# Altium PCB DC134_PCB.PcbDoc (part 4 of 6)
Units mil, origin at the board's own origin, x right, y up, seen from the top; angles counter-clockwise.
Board outline 4000 x 2750 mil, 6 copper layers (L1_Top Layer, L2_GND1, L3_Signal, L4_Plane, L5_GND2, L6_Bottom Layer), stack 60.4 mil thick; 404 components, 244 nets, 1547 pads, 694 vias.
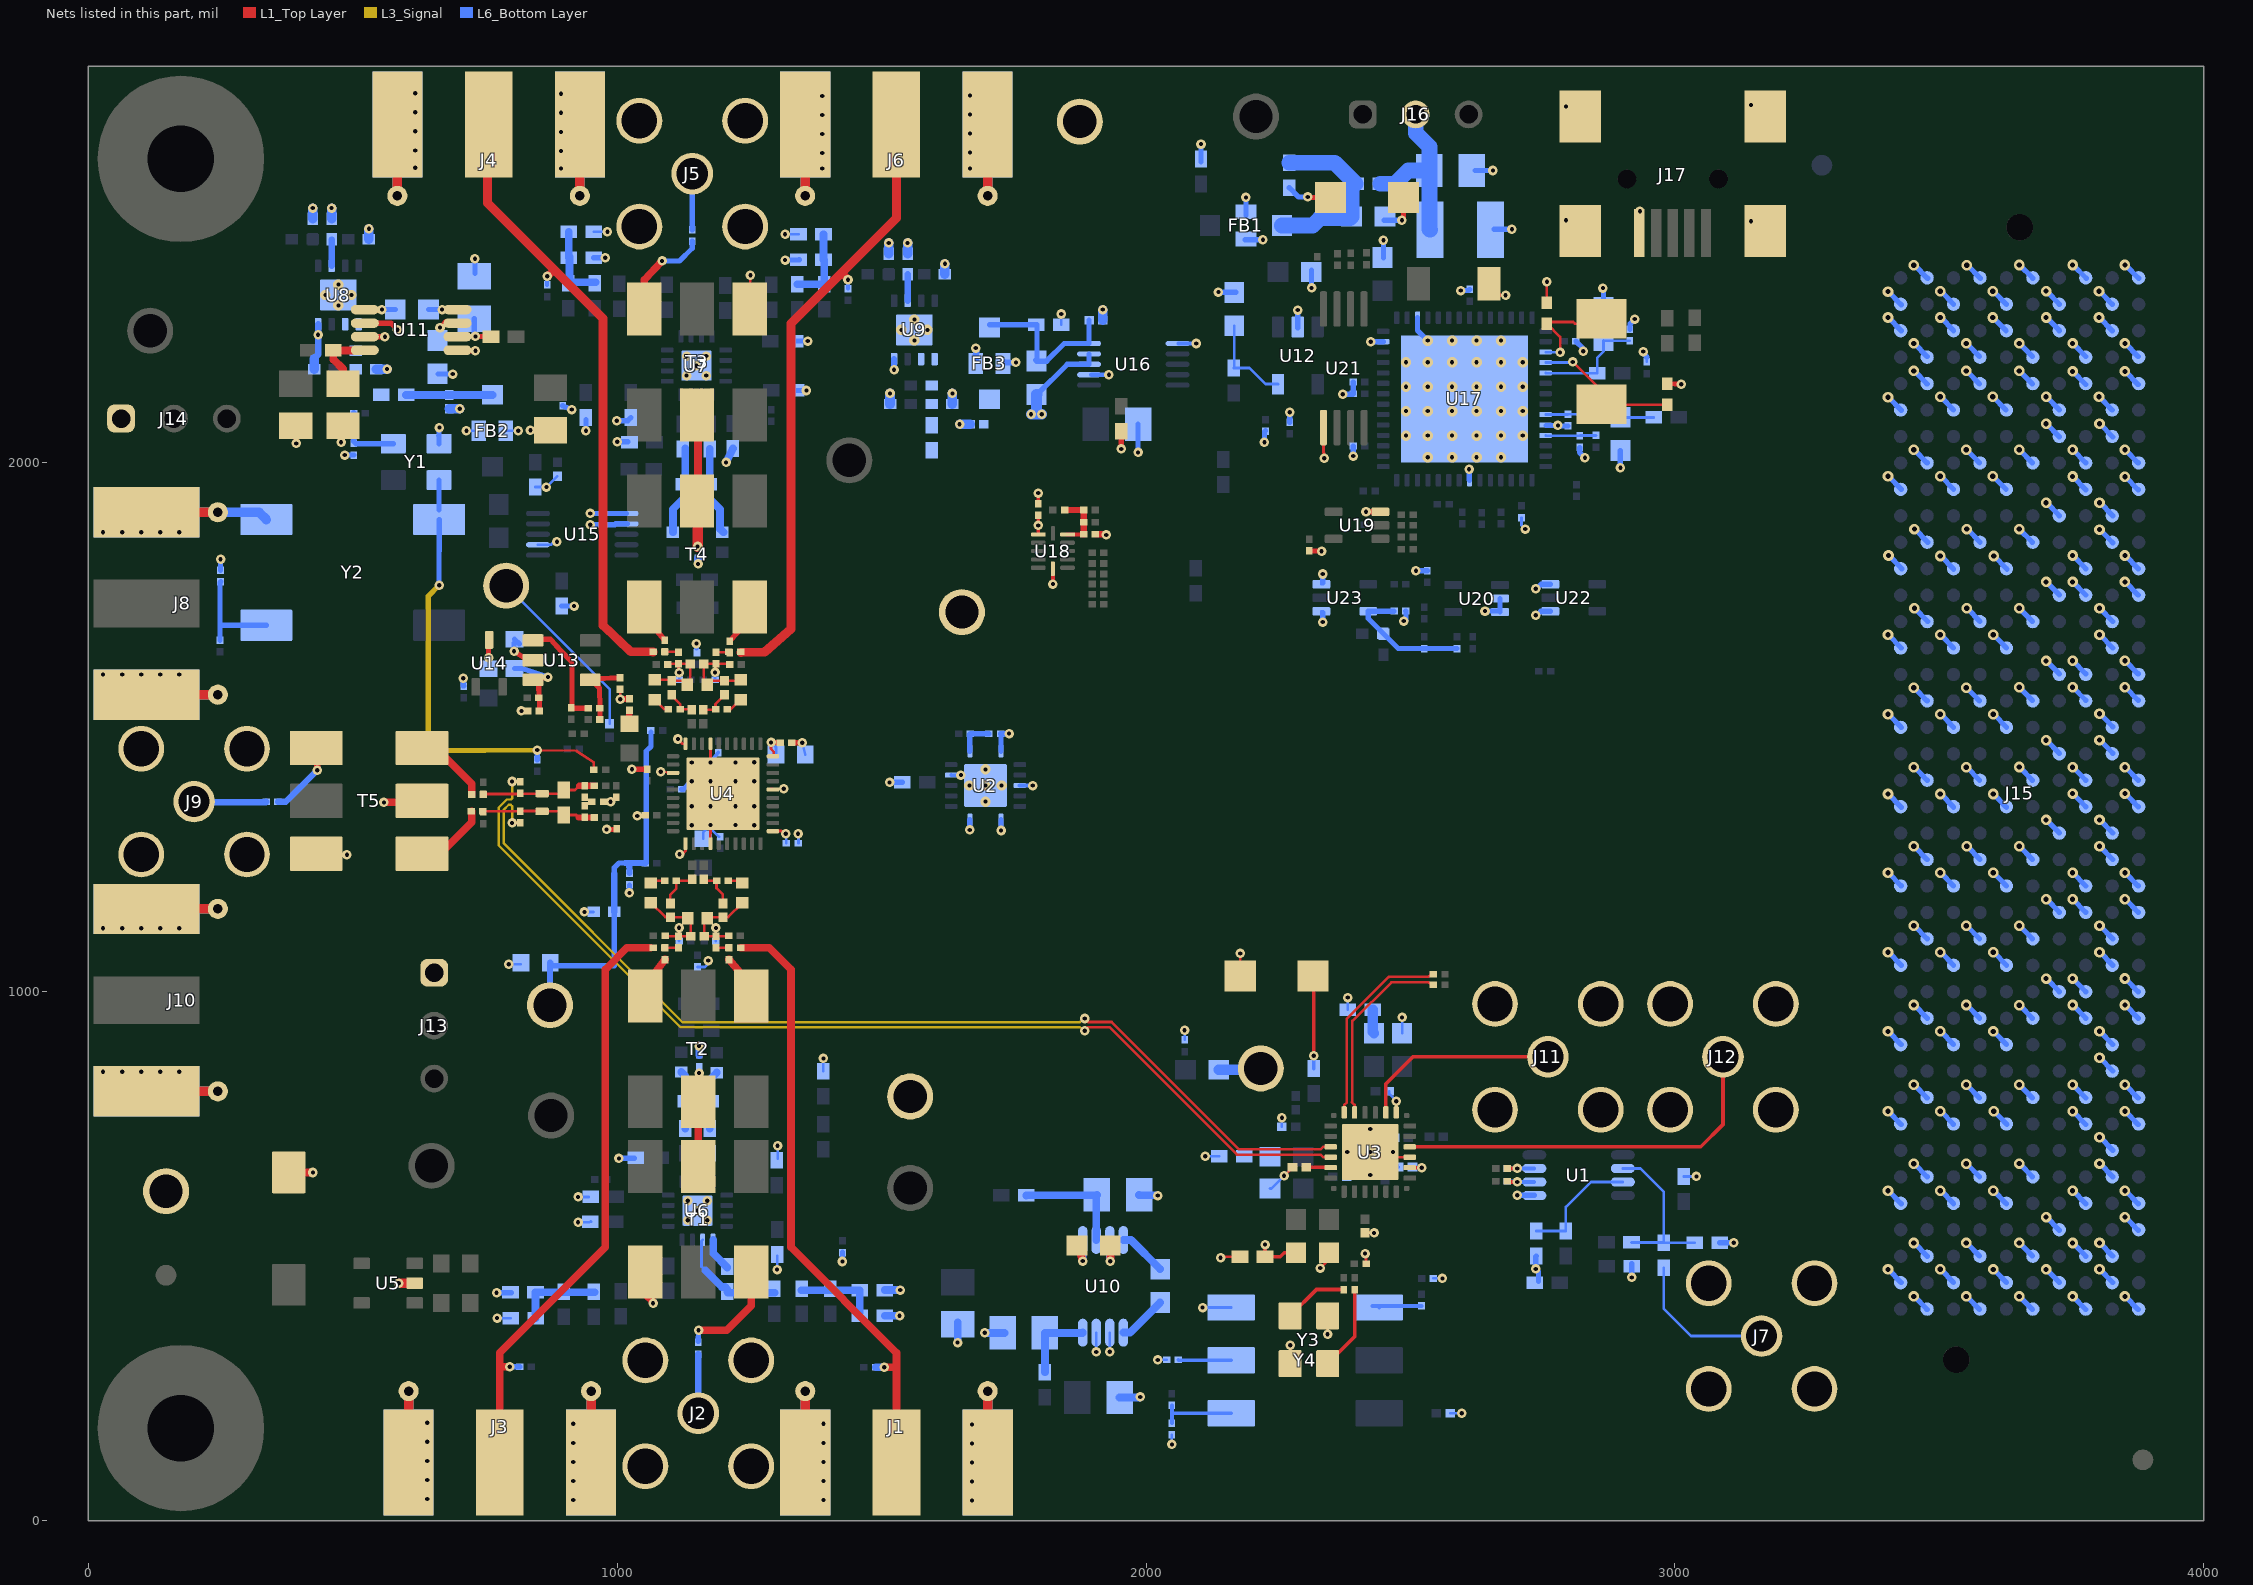
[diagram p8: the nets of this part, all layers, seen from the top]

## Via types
v1: diameter 18, hole 8, L1_Top Layer to L6_Bottom Layer, tented both sides, 448 vias
v2: diameter 20, hole 10, L1_Top Layer to L6_Bottom Layer, tented both sides, 182 vias
v3: diameter 19.68, hole 7.87, L1_Top Layer to L6_Bottom Layer, tented both sides, 42 vias
v4: diameter 19.68, hole 7.87, L1_Top Layer to L6_Bottom Layer, 20 vias
v5: diameter 18, hole 8, L1_Top Layer to L6_Bottom Layer, 2 vias

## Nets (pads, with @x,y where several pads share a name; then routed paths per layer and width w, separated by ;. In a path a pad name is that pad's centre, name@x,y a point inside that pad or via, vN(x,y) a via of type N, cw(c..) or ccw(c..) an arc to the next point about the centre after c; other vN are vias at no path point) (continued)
GND: C5.1 C7.1 C13.1 C15.1 C18.1 C19.1 C20.1 C22.1 C24.1 C27.2 C28.2 C29.2 C30.2 C31.2 C32.2 C33.2 C34.2 C35.2 C36.2 C37.2 C38.2 C39.2 C40.2 C41.2 C42.2 C43.2 C45.2 C46.2 C47.2 C48.2 C49.1 C50.1 C53.2 C54.1 C55.1 C58.2 C59.2 C60.2 C61.2 C62.2 C63.2 C64.2 C65.2 C66.2 C67.2 C68.2 C69.2 C70.2 C71.1 C72.1 C73.1 C74.2 C75.2 C76.2 C77.1 C78.2 C79.2 C80.2 C83.2 C84.2 C85.2 C86.1 C87.2 C88.2 C89.2 C90.2 C91.2 C92.2 C93.2 C94.2 C95.2 C96.2 C97.2 C99.2 C100.2 C101.2 C102.2 C103.2 C104.2 C105.1 C106.1 C107.1 C108.2 C109.1 C110.1 C111.2 C112.1 C113.2 C114.1 C115.2 C116.2 C117.2 C118.2 C119.2 C120.1 C121.2 C122.2 C123.2 C124.2 C125.1 C126.1 D1.1 D2.1 FB1.2 FB2.2 FB3.2 J1.2 J1.3 J1.4 J1.5 J2.2 J2.3 J2.4 J2.5 J3.2 J3.3 J3.4 J3.5 J4.2 J4.3 J4.4 J4.5 J5.2 J5.3 J5.4 J5.5 J6.2 J6.3 J6.4 J6.5 J7.2 J7.3 J7.4 J7.5 J8.2 J8.3 J8.4 J8.5 J9.2 J9.3 J9.4 J9.5 J10.2 J10.3 J10.4 J10.5 J11.2 J11.3 J11.4 J11.5 J12.2 J12.3 J12.4 J12.5 J13.1 J14.1 J15.A1 J15.A4 J15.A5 J15.A8 J15.A9 J15.A12 J15.A13 J15.A16 J15.A17 J15.A20 J15.A21 J15.A24 J15.A25 J15.A28 J15.A29 J15.A32 J15.A33 J15.A36 J15.A37 J15.A40 J15.B2 J15.B3 J15.B6 J15.B7 J15.B10 J15.B11 J15.B14 J15.B15 J15.B18 J15.B19 J15.B22 J15.B23 J15.B26 J15.B27 J15.B30 J15.B31 J15.B34 J15.B35 J15.B38 J15.B39 J15.C1 J15.C4 J15.C5 J15.C8 J15.C9 J15.C12 J15.C13 J15.C16 J15.C17 J15.C20 J15.C21 J15.C24 J15.C25 J15.C28 J15.C29 J15.C32 J15.C33 J15.C36 J15.C38 J15.C40 J15.D2 J15.D3 J15.D6 J15.D7 J15.D10 J15.D13 J15.D16 J15.D19 J15.D22 J15.D25 J15.D28 J15.D37 J15.D39 J15.E1 J15.E4 J15.E5 J15.E8 J15.E11 J15.E14 J15.E17 J15.E20 J15.E23 J15.E26 J15.E29 J15.E32 J15.E35 J15.E38 J15.E40 J15.F2 J15.F3 J15.F6 J15.F9 J15.F12 J15.F15 J15.F18 J15.F21 J15.F24 J15.F27 J15.F30 J15.F33 J15.F36 J15.F39 J15.G1 J15.G4 J15.G5 J15.G8 J15.G11 J15.G14 J15.G17 J15.G20 J15.G23 J15.G26 J15.G29 J15.G32 J15.G35 J15.G38 J15.G40 J15.H2 J15.H3 J15.H6 J15.H9 J15.H12 J15.H15 J15.H18 J15.H21 J15.H24 J15.H27 J15.H30 J15.H33 J15.H36 J15.H39 J15.J1 J15.J4 J15.J5 J15.J8 J15.J11 J15.J14 J15.J17 J15.J20 J15.J23 J15.J26 J15.J29 J15.J32 J15.J35 J15.J38 J15.J40 J15.K2 J15.K3 J15.K6 J15.K9 J15.K12 J15.K15 J15.K18 J15.K21 J15.K24 J15.K27 J15.K30 J15.K33 J15.K36 J15.K39 J17.5 J17.6 J17.7 J17.8 J17.9 R33.1 R37.1 R39.1 R44.1 R46.1 R54.1 R55.1 R58.1 R62.1 R67.1 R68.2 R69.1 R70.2 R71.1 R73.1 R74.1 R78.1 R81.2 R89.1 R94.2 R95.1 R98.2 R106.1 R111.2 R112.1 R121.1 R122.1 R127.1 R132.1 R154.1 R175.1 R176.1 S1.1 T1.1 T3.1 T5.3 T5.5 TP3.1 TP4.1 TP5.1 U1.5 U2.1 U2.5 U2.8 U2.11 U2.14 U2.15 U3.9 U3.13 U3.25 U4.3 U4.11 U4.14 U4.26 U4.37 U4.40 U4.41 U5.2 U6.17@1151.92,586.12 U7.17@1149.84,2184 U8.4 U8.9 U9.4 U9.9 U10.2 U10.3 U10.5 U11.2 U11.3 U11.5 U12.2 U13.2 U14.3 U15.1 U15.2 U15.7 U16.1 U16.7 U17.10 U17.21 U17.41 U17.45 U17.57 U18.6 U19.3 U20.2 U20.3 U21.5 U22.1 U22.3 U23.1 U23.3 Y1.2 Y2.2 Y3.2 Y3.4 Y4.3 | length 11308.1
  L1_Top Layer w5: T5.3@424,1259 v1(489,1259) ; R127.1@1005.4,1572 1006,1571.4 v1(1006,1553) ; v1(1082.5,1416) U4.3@1103.84,1414.07 ; U4.3@1103.54,1414.37 U4.3@1103.84,1414.07 ; U4.3@1103.91,1414 U4.3@1103.84,1414.07 ; U4.3@1105.63,1413.91 U4.3@1103.84,1414.07 ; v1(1115,1478) 1123.97,1469.03 U4.40@1129.25,1469.03 ; v1(1118.08,1260) 1123.13,1260 1129.25,1266.12 U4.11@1129.25,1280.06 ; U4.41@1160.66,1414 U4.41@1200.12,1374.54 U4.41@1208.45,1382.87 ; U4.14@1175.98,1278.17 1176,1280.06 U4.41@1176.37,1315.49 ; U4.41@1176.38,1434.06 U4.37@1176.38,1469.49 ; T3.1@1251,2291 1252,2292 v1(1252,2355) ; U4.26@1292.22,1384 1290.64,1382.42 1294.59,1382.67 v1(1315,1384) ; U4.26@1294.36,1383 U4.26@1294.49,1382.87 ; v1(2141,497) 2143,499 C27.2@2177.88,499 ; D1.1@2178.1,1030 v1(2178.1,1072.48) ; v1(2261,651.99) R73.1@2277.01,668 ; Y3.2@2272.57,296.72 v1(2272.57,331.57) ; v1(2329.57,477.57) 2346.26,494.26 C28.2@2346.26,506.5 ; U21.5@2335.61,2066.8 2335.61,2019.41 2337,2018.03 v1(2337,2009) ; v1(2343.43,352.43) Y3.4@2343.43,387.28 ; v1(2414.16,505) 2416.02,501.98 R70.2@2416.02,486 ; C29.2@2414.16,544.01 v1(2431.2,544.01) ; v3(2424,697) 2433.84,687.16 U3.9@2498.8,687.16 ; U3.13@2473.21,771.8 v1(2473.21,793.21) ; C104.2@2648.93,2339 2670.93,2317 ; C104.2@2665.93,2316 v1@2675,2316 ; C118.2@2758,2302.69 v1(2758,2342.5) ; J17.5@2933.01,2416.64 J17.5@2934,2417.63
  L1_Top Layer w7: C116.2@1796.24,1924.02 v1(1796.24,1943) ; v1(1824,1771) U18.6@1824,1799.83
  L1_Top Layer w10: v1(393,2037) C95.2@393,2075 ; v1(478,2039) C96.2@478,2077 ; U11.3@522.9,2238.7 v1(560.9,2238.7) ; U11.2@522.9,2264.29 572.21,2264.29 v1(584.5,2252) ; U11.5@694,2212 v1(732,2212) ; v1(756.78,1632) 756.78,1664.07 U14.3@758,1665.29 ; v1(805,1644) 828.52,1629 U13.2@850.71,1629 ; v1(819,1531) R132.1@830.98,1531 ; v1(836,2062) C90.2@874,2062 ; v1(980,1307) R54.1@999.87,1307 ; v1(1028,1421) C45.2@1057,1421.02 ; C37.2@1332.02,1471 v1(1350,1471) ; v1(1953,2026.5) C103.2@1953,2059.88 ; C121.2@2308.59,1833.98 2310.59,1833.98 v1(2332,1833) ; U21.5@2335.61,2066.8 U21.5@2337,2065.41 ; v1(2416,1907.59) U19.3@2443.29,1907.59 U19.3@2445.29,1907.59 ; v1(2484,2459) 2486.9,2461.9 D2.1@2486.9,2502 ; J17.5@2934,2417.63 v1(2934,2476) ; C119.2@2982,2150.5 2986.03,2150.3 v1(3012,2149)
  L1_Top Layer w12: v1(1006,1553) R78.1@1023.34,1553.85 ; C115.2@1906.02,1865 v1@1924,1865
  L1_Top Layer w15: S1.1@379,658.3 v1(424.7,658.3) ; v1(559,1358) T5.5@620,1359 ; T1.1@1053.37,470 1053.37,428.63 v1@1069,413 ; C91.2@1870.89,520.89 v1(1880.39,490.89)
  L1_Top Layer w18: v1(587.2,449) U5.2@617.2,449
  L6_Bottom Layer w5: J4.4@574,2704.62 577.38,2708 J4.4@603,2708 ; Y1.2@660.31,2051.31 Y1.2@661,2052 ; v1(714.89,2060.89) FB2.2@738.41,2060.89 ; v5(773,383) R94.2@798.88,383 ; FB2.2@789.59,2060.89 v1(813,2060.89) ; v1(795,1052) C47.2@817.13,1052 ; C75.2@845,1954.38 v1(866.38,1954.38) C76.2@887,1975.01 ; U15.7@850.34,1845.39 875,1845.39 880.68,1851.08 v1(886,1851.08) ; v1(926,564.01) C65.2@947.31,564.01 ; v1(926,612) C66.2@946.08,612 ; v1(938,1151) C46.2@955.31,1151 ; C65.2@949.76,566 C65.2@950.45,565.31 ; R98.2@955.62,2437 v1(981.5,2437) ; C5.1@1152,1046.98 1166,1046.98 1172.44,1053.42 v1(1172.44,1059) ; C43.2@1163,1289.56 1163,1301.99 v4(1176.5,1315.49) ; v4@1179.73,1306.29 C41.2@1193,1293.02 ; v1(1302.45,474.76) C59.2@1302.45,500.38 ; C60.2@1303.45,684.58 v1(1303.45,709) ; v1(1317.5,2432.5) R111.2@1342.88,2432.5 ; C38.2@1343,1281 v1@1343,1298.02 ; v1(1350,1471) C39.2@1355.43,1448.56 ; R89.1@1390,849.58 v1(1390,874) ; C79.2@1839.62,2261 v1(1839.62,2281.62) ; v1(1905.98,319.02) U10.3@1905.98,355.4 ; v1(1931.57,319.45) U10.2@1931.57,355.4 ; v1@1988,233 v1(1989,234) ; v1(2022,304) R68.2@2038.98,304 ; v1(2049,144) R69.1@2049,161.98 ; C100.2@2073,909.02 v1(2073,927.15) ; v1(2107,403) Y4.3@2161.04,403 ; v1(2112,689) C31.2@2138.38,689 ; C32.2@2234.45,628 2237.01,628 v1(2261,651.99) ; R58.1@2257.01,745 v1(2257.01,762.01) ; C86.1@2272,2077.11 C86.1@2272.09,2077.02 ; U23.1@2331.71,1719.43 U23.1@2334,1717.14 ; U23.3@2331.71,1770.61 U23.3@2334.02,1772.93 ; C33.2@2379.49,650.15 2420.45,650.15 v3(2424,653.69) ; C34.2@2381.38,966 v1(2381.38,989) ; C107.1@2390.98,2130 C107.1@2391.98,2131 ; v1@2412.07,504.07 v1@2413,505 ; C36.2@2459.99,811.75 2459.99,806.43 v1(2473.21,793.21) ; R74.1@2470.01,724 2470.01,699.7 v3(2467.31,697) 2452,681.69 R62.1@2452,670.99 2475.49,670.99 R71.1@2478.01,668.47 ; C35.2@2484.32,921.5 v1(2484.32,951.52) ; R67.1@2543.52,458 v1(2560.5,458) ; C30.2@2574.99,203 v1(2597,203) ; U20.3@2667.45,1719.98 U20.3@2669.4,1718.03 ; C106.1@2710,1896.57 2710,1882 v1(2717,1875) ; v1(2737,1712) v1@2738,1711 ; v1(2737,1762) v1@2738.41,1762 ; U17.10@2755.56,2071.79 U17.10@2756.35,2071 ; v1(2779,2071) v1@2780.02,2069.98 ; v1(2827,2211) v1@2827,2216.02 ; v1(2864,2330.61) v1@2865,2329.61 ; v1@2940.17,2206.83 v1(2940.17,2210.62) ; R154.1@2947,2191.02 2947,2200 ; v1(3040.77,650.77) C22.1@3017,650.77 3040.77,651 v1@3041,651
  L6_Bottom Layer w7: v4@1176.38,1434.06 1190.79,1452.14 1191,1452.4 C42.2@1191,1451.98 ; U2.5@1631.51,1409.88 U2.5@1631.51,1409.73 v1(1650,1409.73)
  L6_Bottom Layer w8: U2.11@1761.44,1390.04 1761.48,1390 v1(1786,1390) ; U16.7@1896.62,2166.81 v1(1930,2166.81) ; U16.1@2061.62,2225.87 v1(2095,2225.87)
  L6_Bottom Layer w10: R39.1@250,1797.02 v1(250,1818) ; v1(485,2015) R33.1@502,2014.98 ; C92.2@661.69,2168 v1(689,2168) ; Y1.2@663.31,2036.45 v1@663.31,2066.31 ; v1(709,1593) 709,1578.81 C97.2@709.78,1578.02 ; C89.2@731,2358.69 v1(731,2386) ; v1(772,431) C53.2@800.38,431 ; v1(805,1644) C101.2@805,1659.04 ; C101.2@806,1666.56 C101.2@815,1657.56 ; C102.2@895,1729.38 v1(918.62,1729.38) ; R112.1@897,2107.98 v1(914,2101) ; v1(941,2060.89) C61.2@941,2081.64 ; v1@949,1883 v1(949.08,1883) 993.45,1883 ; v1(949.08,1904.45) U15.1@1017.66,1904.45 ; C54.1@955.62,2388 v1(977.38,2388) ; U15.2@995.45,1883.24 997.21,1885 U15.2@1019.66,1885 ; v1(999.38,2080) 1020.13,2080 C62.2@1026.09,2085.96 ; v1(1000.28,2040) R106.1@1020.66,2040 ; v1(1003.45,685) C50.1@1032.83,685 ; v1(1023.33,1187) C48.2@1023.33,1201.87 ; C40.2@1122.02,1383 1125.32,1383 v4@1140.94,1398.62 ; v1@1150,1650.02 v1(1150,1658.55) ; v1(1317.5,2383.5) C58.2@1344.38,2384.38 ; C63.2@1336.62,2230.5 v1(1360.5,2230.5) ; C64.2@1338.62,2137 v1(1358,2137) ; v1(1426,490) R95.1@1426,508.1 ; v1(1515,1396) C18.1@1539.38,1396 ; v1(1666.94,1306) U2.1@1666.94,1325.08 ; v1(1726,1305) U2.14@1726,1325.08 ; U2.8@1726,1455 1726,1487.21 R55.1@1725.02,1488.19 v1(1741.19,1488.19) ; v1(1985,2020) C85.2@1985,2073 ; C70.2@2104,2569.62 C70.2@2104,2574.62 v1(2104,2603) ; v1(2137,2323) C84.2@2170.38,2323 ; FB1.2@2187.62,2422 v1(2221,2422) ; FB1.2@2189,2468.62 FB1.2@2189,2474.59 v1(2189,2502) ; v1(2224,2039) 2224,2058.89 C123.2@2226,2060.89 ; C86.1@2272,2077.11 v1(2272,2096) ; U12.2@2287,2255.62 v1(2287,2289) ; v1(2313,2331) C83.2@2313,2364.38 ; v1(2334,1699) U23.1@2334,1717.14 ; U23.3@2334,1772.95 v1(2334,1790) ; v1(2372,2130) C107.1@2390.98,2130 ; v1(2391.98,2013.05) C110.1@2391.98,2032 ; C107.1@2391.98,2131 C120.1@2391.98,2153.12 ; v1(2425,2229.27) U17.41@2448.47,2229.27 ; C108.2@2449.02,2387.62 v1(2449.02,2421) ; C69.2@2450.62,2459 v1(2484,2459) ; v1@2484.85,1701 v1(2487.17,1701) ; C124.2@2491.02,1720 2491.68,1719.29 v1@2491.68,1702 ; v1(2510.39,1796.02) C122.2@2532,1796.02 ; U17.45@2513.43,2274.54 2513.44,2250.65 v3(2532.75,2231.33) ; v1(2595,2326) 2609.98,2326 C105.1@2612,2328.02 ; v1(2611,1988) 2611,1968.32 U17.21@2611.86,1967.46 ; C68.2@2622.62,2553 v1(2656,2553) ; v1(2641,1720) U20.3@2667.43,1720 ; C67.2@2658.62,2441.91 v1(2692,2441.91) ; U20.3@2669.4,1718.03 U20.2@2669.4,1743.62 ; v1(2702,615.15) 2733.95,615.15 U1.5@2734.34,614.76 ; R44.1@2738,500.38 2737,499.38 v1(2737,476) 2742.38,470.62 C19.1@2742.38,452 ; v1@2738,1711 2746.41,1719.41 U22.1@2764.71,1719.41 ; v1@2738.41,1762 2747,1770.59 U22.3@2764.71,1770.59 ; U17.10@2756.35,2071 v1(2779,2071) ; v1@2780.02,2069.98 C112.1@2798,2069.98 ; C109.1@2813.02,2230 v1@2827,2216.02 ; C117.2@2820,2029.35 2820,2020 v1(2830,2010) ; C113.2@2865,2294.5 v1@2865,2329.61 ; v1(2897,1991) C111.2@2897,2023.5 ; C114.1@2915,2253.02 2915,2263 v1(2924,2272) ; v1(2918.62,460) C20.1@2918.62,481 C20.1@2918.62,486.38 ; v1@2940.17,2206.83 2947,2200 ; R37.1@3085,525.62 v1(3111.38,525.62) ; v2@3404,475 3427.59,450.57 J15.K39@3428,450.15 ; v2@3404,624 3427.09,600.09 J15.K36@3428,599.15 ; v2@3404,774 3427.09,750.09 J15.K33@3428,749.15 ; v2@3404,925 3427.59,900.57 J15.K30@3428,900.15 ; v2@3404,1075 3427.59,1050.57 J15.K27@3428,1050.15 ; v2@3404,1225.17 3427.67,1200.65 J15.K24@3428,1200.31 ; v2@3404,1374 3427.09,1350.09 J15.K21@3428,1349.15 ; v2@3404,1524.8 3427.49,1500.47 J15.K18@3428,1499.95 ; v2@3404,1675 3427.59,1650.57 J15.K15@3428,1650.15 ; v2@3404,1975 3427.59,1950.57 J15.K9@3428,1950.15 ; v2@3404,2124.34 3427.26,2100.25 J15.K6@3428,2099.49 ; v2@3404,2275 3427.59,2250.57 J15.K3@3428,2250.15 ; v2@3404,2324 3427.09,2300.09 J15.K2@3428,2299.15 ; v2@3405,1825 3428.11,1801.07 J15.K12@3429,1800.15 ; v2@3453,424 3476.57,399.59 J15.J40@3477,399.15 ; v2@3453,525 J15.J38@3477,500.15 ; v2@3453,675 J15.J35@3477,650.15 ; v2@3453,824 3476.57,799.59 J15.J32@3477,799.15 ; v2@3453,975.06 J15.J29@3477,950.21 ; v2@3453,1125 J15.J26@3477,1100.15 ; v2@3453,1274.98 J15.J23@3477,1250.13 ; v2@3453,1424.76 J15.J20@3477,1400 J15.J20@3477,1399.9 ; v2@3453,1575 J15.J17@3477,1550.15 ; v2@3453,2025 J15.J8@3477,2000.15 ; v2@3453,2174 3476.57,2149.59 J15.J5@3477,2149.15 ; v2@3453,2226 J15.J4@3477,2201.15 ; v2@3453,2374 J15.J1@3478,2349 ; v2@3454,1725 3477.59,1700.57 J15.J14@3478,1700.15 ; v2@3454,1875 3477.59,1850.57 J15.J11@3478,1850.15 ; v2@3503,475.15 J15.H39@3527,450.3 ; v2@3503,624 3526.57,599.59 J15.H36@3527,599.15 ; v2@3503,774 3526.57,749.59 J15.H33@3527,749.15 ; v2@3503,925.15 J15.H30@3527,900.3 ; v2@3503,1075 J15.H27@3527,1050.15 ; v2@3503,1225.17 J15.H24@3527,1200.31 ; v2@3503,1374 3526.57,1349.59 J15.H21@3527,1349.15 ; v2@3503,1525 J15.H18@3527,1500.15 ; v2@3503,1675 J15.H15@3527,1650.15 ; v2@3503,1824 3526.57,1799.59 J15.H12@3527,1799.15 ; v2@3503,1975 J15.H9@3527,1950.15 ; v2@3503,2125 J15.H6@3527,2100.15 ; v2@3503,2275 J15.H3@3527,2250.15 ; v2@3503,2324.85 J15.H2@3527,2300 ; v2@3552,424 J15.G40@3576,399.15 ; v2@3552,525.15 J15.G38@3576,500.3 ; v2@3552,675 J15.G35@3576,650.15 ; v2@3552,824 J15.G32@3576,799.15 ; v2@3552,975 J15.G29@3576,950.15 ; v2@3552,1125 J15.G26@3576,1100.15 ; v2@3552,1424.78 J15.G20@3576,1399.92 ; v2@3552,1575 J15.G17@3576,1550.15 ; v2@3552,2025 J15.G8@3576,2000.15 ; v2@3552,2174 J15.G5@3576,2149.15 ; v2@3552,2226 J15.G4@3576,2201.15 ; v2@3553,1274.98 J15.G23@3577,1250.13 ; v2@3553,1725 J15.G14@3577,1700.15 ; v2@3553,1875 J15.G11@3577,1850.15 ; v2@3553,2374 J15.G1@3578,2349 ; v2@3602,1975 J15.F9@3626,1950.15 ; v2@3602,2125 J15.F6@3626,2100.15 ; v2@3602,2275 J15.F3@3626,2250.15 ; v2@3602,2324.85 J15.F2@3627,2299.85 ; v2@3603,475 J15.F39@3627,450.15 ; v2@3603,624 3626.57,599.59 J15.F36@3627,599.15 ; v2@3603,925 J15.F30@3627,900.15 ; v2@3603,1075 J15.F27@3627,1050.15 ; v2@3603,1225 J15.F24@3627,1200.15 ; v2@3603,1374 3626.57,1349.59 J15.F21@3627,1349.15 ; v2@3603,1525 J15.F18@3627,1500.15 ; v2@3603,1675 J15.F15@3627,1650.15 ; v2@3604,774 3627.09,750.09 J15.F33@3628,749.15 ; v2@3604,1824 3627.09,1800.09 J15.F12@3628,1799.15 ; v2(3651,1875) J15.E11@3676,1850 ; v2@3652,424 J15.E40@3676,399.15 ; v2@3652,525.15 J15.E38@3676,500.3 ; v2@3652,675.15 J15.E35@3676,650.3 ; v2@3652,824 J15.E32@3676,799.15 ; v2@3652,974.8 J15.E29@3676,949.95 ; v2@3652,1125 J15.E26@3676,1100.15 ; v2@3652,1275.18 J15.E23@3676,1250.33 ; v2@3652,1425 J15.E20@3676,1400.15 ; v2@3652,1575.67 J15.E17@3676,1550.82 ; v2@3652,1725 J15.E14@3676,1700.15 ; v2@3652,2025 J15.E8@3676,2000.15 ; v2@3652,2174 J15.E5@3676,2149.15 ; v2@3652,2226 J15.E4@3676,2201.15 ; v2@3652,2374.22 J15.E1@3677,2349.22 ; v2@3703,475 J15.D39@3727,450.15 ; v2@3703,574 3726.57,549.59 J15.D37@3727,549.15 ; v2@3703,1025 J15.D28@3727,1000.15 ; v2@3703,1175.17 J15.D25@3727,1150.31 ; v2@3703,1325 J15.D22@3727,1300.15 ; v2@3703,1475.61 J15.D19@3727,1450.75 ; v2@3703,1625.67 J15.D16@3727,1600.82 ; v2@3703,1775 J15.D13@3727,1750.15 ; v2@3703,1925 J15.D10@3727,1900.15 ; v2@3703,2074.26 3726.7,2049.71 J15.D7@3727,2049.4 ; v2@3703,2125 J15.D6@3727,2100.15 ; v2@3703,2275 J15.D3@3727,2250.15 ; v2@3703,2325 J15.D2@3727,2300 ; v2@3753,424 3776.57,399.59 J15.C40@3777,399.15 ; v2@3753,525 J15.C38@3777,500.15 ; v2@3753,624 3776.57,599.59 J15.C36@3777,599.15 ; v2@3753,774 3776.57,749.59 J15.C33@3777,749.15 ; v2@3753,824 3776.57,799.59 J15.C32@3777,799.15 ; v2@3753,975 J15.C29@3777,950.15 ; v2@3753,1025 J15.C28@3777,1000.15 ; v2@3753,1175 J15.C25@3777,1150.15 ; v2@3753,1225 J15.C24@3777,1200.15 ; v2@3753,1374.76 J15.C21@3777,1350 J15.C21@3777,1349.9 ; v2@3753,1424.76 J15.C20@3777,1400 J15.C20@3777,1399.9 ; v2@3753,1576 J15.C17@3777,1551.15 ; v2@3753,1626 J15.C16@3777,1601.15 ; v2@3753,1775 J15.C13@3777,1750.15 ; v2@3753,1825 J15.C12@3777,1800.15 ; v2@3753,1974.42 3776.78,1949.79 J15.C9@3777,1949.57 ; v2@3753,2025 J15.C8@3777,2000.15 ; v2@3753,2173 3776.07,2149.11 J15.C5@3777,2148.15 ; v2@3753,2226 J15.C4@3777,2201.15 ; v2@3753,2374.22 J15.C1@3778,2349.22 ; v2@3803,2125 J15.B6@3827,2100.15 ; v2@3803,2275 J15.B3@3827,2250.15 ; v2@3803,2324.85 J15.B2@3827,2300 ; v2@3804,475.15 3827.67,450.64 J15.B39@3828,450.3 ; v2@3804,525.15 3827.67,500.64 J15.B38@3828,500.3 ; v2@3804,675.15 3827.67,650.64 J15.B35@3828,650.3 ; v2@3804,725.15 3827.67,700.64 J15.B34@3828,700.3 ; v2@3804,875.15 3827.67,850.64 J15.B31@3828,850.3 ; v2@3804,925.15 3827.67,900.64 J15.B30@3828,900.3 ; v2@3804,1075 3827.59,1050.57 J15.B27@3828,1050.15 ; v2@3804,1125 3827.59,1100.57 J15.B26@3828,1100.15 ; v2@3804,1275 3827.59,1250.57 J15.B23@3828,1250.15 ; v2@3804,1325 3827.59,1300.57 J15.B22@3828,1300.15 ; v2@3804,1476 J15.B19@3828,1451.15 ; v2@3804,1526 J15.B18@3828,1501.15 ; v2@3804,1675 3827.59,1650.57 J15.B15@3828,1650.15 ; v2@3804,1725 3827.59,1700.57 J15.B14@3828,1700.15 ; v2@3804,1874 3827.09,1850.09 J15.B11@3828,1849.15 ; v2@3804,1925 3827.59,1900.57 J15.B10@3828,1900.15 ; v2@3804,2074 3827.09,2050.09 J15.B7@3828,2049.15 ; v2@3852,424 J15.A40@3876,399.15 ; v2@3852,574 J15.A37@3876,549.15 ; v2@3852,624 J15.A36@3876,599.15 ; v2@3852,774 J15.A33@3876,749.15 ; v2@3852,824 J15.A32@3876,799.15 ; v2@3852,975.06 J15.A29@3876,950.21 ; v2@3852,1025.06 J15.A28@3876,1000.21 ; v2@3852,1175.17 J15.A25@3876,1150.31 ; v2@3852,1225.17 J15.A24@3876,1200.31 ; v2@3852,1374.78 J15.A21@3876,1349.92 ; v2@3852,1424.78 J15.A20@3876,1399.92 ; v2@3852,1576 J15.A17@3876,1551.15 ; v2@3852,1626 J15.A16@3876,1601.15 ; v2@3852,1775 J15.A13@3876,1750.15 ; v2@3852,1825 J15.A12@3876,1800.15 ; v2@3852,1974 J15.A9@3876,1949.15 ; v2@3852,2025 J15.A8@3876,2000.15 ; v2@3852,2173 3875.56,2148.61 J15.A5@3876,2148.15 ; v2@3852,2226 J15.A4@3876,2201.15 ; v2@3852,2374.22 J15.A1@3877,2349.22
  L6_Bottom Layer w12: 426.8,2197.39 434.48,2205.06 v1(434.48,2242.39) U8.4@434.48,2262.39 ; v1(1523.61,2176.41) U9.4@1523.61,2196.41 ; FB3.2@1677.85,2195.13 v1@1678.95,2217.08 ; FB3.2@1732,2190.12 v1@1753.95,2189.02
  L6_Bottom Layer w14.5: v1(1153,1809) C15.1@1153,1819.73 ; C7.1@1155,880.52 v1(1155,897.37) v1@1155,900 ; v1(1206,2001.02) C55.1@1219,2027.38 ; C49.1@1505.95,436 v1(1535.32,436) ; R81.2@1506,387.5 v5(1534,387.5)
  L6_Bottom Layer w15: v1@1644,337 C88.2@1644,374.37 ; v1@1695.4,355 C94.2@1732.78,355 ; v1(1880.39,490.89) U10.5@1880.39,530.6 ; C93.2@1950,233 v1@1988,233 ; C87.2@1987,616 v1@2022,615
  L6_Bottom Layer w18: J8.3@240,1906.75 322.86,1906.75 Y2.2@336.61,1893 ; R121.1@424.48,2461.99 v1(424.48,2481.99) ; R175.1@426.8,2177.39 426.8,2197.39 ; C125.1@460.07,2461.99 v1(460.07,2481.99) ; C73.1@530.74,2422.62 v1(530.74,2442.62) ; C71.1@544.91,2177.39 v1(564.91,2177.39) ; C74.2@682.35,2102.52 v1(702.35,2102.52) ; R122.1@1513.61,2396.02 v1(1513.61,2416.02) ; R176.1@1515.94,2111.41 v1(1515.94,2131.41) ; C126.1@1549.2,2396.02 v1(1549.2,2416.02) ; C77.1@1619.87,2356.65 v1(1619.87,2376.65) ; C72.1@1634.05,2111.41 v1(1634.05,2131.41) ; v1(1647.52,2073) C78.2@1667.52,2073 ; C80.2@1918.32,2270.01 v1(1918.32,2290.01)
  other v1: 1671,38 917,39 1390,39 641,41 1671,74 917,75 1390,75 641,77 1671,110 917,111 1390,111 641,113 1671,146 917,147 1390,147 641,149 1671,182 917,183 1390,183 641,185 1643.6,336.6 1695,355.4 1068,411.16 1133.45,568 1170.45,568 1151.92,586.12 1133.45,605 1170.45,605 2022.4,614.6 28,849 64,849 100,849 136,849 172,849 28,1120 64,1120 100,1120 136,1120 172,1120 1342.02,1299 1141,1315 1259.17,1315 987.44,1359.3 1141,1433.6 1259.17,1433.9 28,1599.92 64,1599.92 100,1599.92 136,1599.92 172,1599.92 1925,1864 28,1869 64,1869 100,1869 136,1869 172,1869 664,2067 1131.32,2165.12 1168.32,2165.12 1149.85,2184 1754,2189.97 1131.32,2202.12 1168.32,2202.12 1678,2217.13 2680,2317 3144,2457 2794,2459 894,2557 1388,2557 1667,2557 618,2558 1388,2586 1667,2587 894,2590 618,2591 1388,2622 1667,2623 894,2626 618,2627 1388,2658 1667,2659 894,2662 618,2663 2794,2674 3144,2677 1388,2694 1667,2695 894,2698 618,2699
  other v2: 3452,424 3551,424 3651,424 3752,424 3851,424 3403,475 3502,475.15 3602,475 3702,475 3803,475.15 3452,525 3551,525.15 3651,525.15 3752,525 3803,525.15 3702,574 3851,574 3403,624 3502,624 3602,624 3752,624 3851,624 3452,675 3551,675 3651,675.15 3803,675.15 3803,725.15 3403,774 3502,774 3603,774 3752,774 3851,774 3452,824 3551,824 3651,824 3752,824 3851,824 3803,875.15 3403,925 3502,925.15 3602,925 3803,925.15 3452,975.06 3551,975 3651,974.8 3752,975 3851,975.06 3702,1025 3752,1025 3851,1025.06 3403,1075 3502,1075 3602,1075 3803,1075 3452,1125 3551,1125 3651,1125 3803,1125 3702,1175.17 3752,1175 3851,1175.17 3403,1225.17 3502,1225.17 3602,1225 3752,1225 3851,1225.17 3452,1274.98 3552,1274.98 3651,1275.18 3803,1275 3702,1325 3803,1325 3403,1374 3502,1374 3602,1374 3752,1374.76 3851,1374.78 3452,1424.76 3551,1424.78 3651,1425 3752,1424.76 3851,1424.78 3702,1475.61 3803,1476 3403,1524.8 3502,1525 3602,1525 3803,1526 3452,1575 3551,1575 3651,1575.67 3752,1576 3851,1576 3702,1625.67 3752,1626 3851,1626 3403,1675 3502,1675 3602,1675 3803,1675 3453,1725 3552,1725 3651,1725 3803,1725 3702,1775 3752,1775 3851,1775 3502,1824 3603,1824 3404,1825 3752,1825 3851,1825 3803,1874 3453,1875 3552,1875 3702,1925 3803,1925 3752,1974.42 3851,1974 3403,1975 3502,1975 3601,1975 3452,2025 3551,2025 3651,2025 3752,2025 3851,2025 3702,2074.26 3803,2074 3403,2124.34 3502,2125 3601,2125 3702,2125 3802,2125 3752,2173 3851,2173 3452,2174 3551,2174 3651,2174 3452,2226 3551,2226 3651,2226 3752,2226 3851,2226 3403,2275 3502,2275 3601,2275 3702,2275 3802,2275 3403,2324 3502,2324.85 3601,2324.85 3702,2325 3802,2324.85 3452,2374 3552,2374 3651,2374.22 3752,2374.22 3851,2374.22
  other v3: 2380.69,697 2424,740.31 1696.48,1359.53 1665.96,1390.04 1696.48,1390.04 1726.99,1390.04 1696.48,1420.55 2532.75,2010.67 2578.93,2010.67 2625.11,2010.67 2671.29,2010.67 2491.68,2051.73 2532.75,2051.73 2578.93,2051.73 2625.11,2051.73 2671.29,2051.73 2712.35,2051.73 2491.68,2097.91 2532.75,2097.91 2578.93,2097.91 2625.11,2097.91 2671.29,2097.91 2712.35,2097.91 2491.68,2144.09 2532.75,2144.09 2578.93,2144.09 2625.11,2144.09 2671.29,2144.09 2712.35,2144.09 2491.68,2190.27 2532.75,2190.27 2578.93,2190.27 2625.11,2190.27 2671.29,2190.27 2712.35,2190.27 2578.93,2231.33 2625.11,2231.33 2671.29,2231.33
  other v4: 1223.74,1315.49 1141.06,1350.92 1176.5,1350.92 1223.74,1350.92 1259.17,1350.92 1141.06,1398.17 1176.5,1398.17 1223.74,1398.17 1259.17,1398.17 1176.5,1433.6 1223.74,1433.6 1562,2231.84 1537.39,2251.53 1586.61,2251.53 1562,2271.21 472.87,2297.82 448.26,2317.5 497.47,2317.5 472.87,2337.19
HW_SW_CTRL: R73.2 U3.23 | length 46.4
  L1_Top Layer w7: R73.2@2302.99,668 2348.67,668 U3.23@2349.2,667.47
InternalCLK_N: R53.1 U3.21 | length 1944.9
  L1_Top Layer w5: v1(801.38,1319.2) R53.1@817,1319.2 ; v1(1884,949.5) 1890.5,943 1935,943 2176,702 2330.04,702 2334.89,706.84 U3.21@2349.2,706.84
  L3_Signal w4.4: v1(801.38,1319.2) 801.38,1351.26 798.8,1353.84 795.16,1353.84 785.78,1344.46 785.78,1280.31 1123.51,942.57 1874.62,942.57 v1(1884,949.5) v1@1881.55,949.5
InternalCLK_P: R43.1 U3.22 | length 1974.4
  L1_Top Layer w5: v1(801.38,1397.62) R43.1@817,1397.62 ; v1(1884,926.5) 1890.5,933 1930.86,933 2171.86,692 2330.04,692 2334.89,687.16 U3.22@2349.2,687.16
  L3_Signal w4.4: 776.13,1276.52 776.13,1348.25 ; 776.63,1276.02 1119.72,932.93 1874.62,932.93 v1@1884,926 ; 776.63,1348.75 791.37,1363.49 798.8,1363.49 ; 799.5,1363.5 801.38,1365.56 v1(801.38,1397.62) ; v1@1881.55,926.5 v1(1884,926.5)
IOVDD: C37.1 C38.1 C39.1 C116.1 R134.1 TP7.1 U4.21 U4.30 U16.8 U16.9 U18.1 | length 336.7
  L1_Top Layer w5: v1(1291,1471.57) 1291,1459 1296,1454 1296,1447.38 U4.30@1294.49,1445.87 ; U4.21@1294.49,1304.13 1310,1304.13 1315.13,1299 v1(1319,1299)
  L1_Top Layer w7: v1@1796.02,1882.22 C116.1@1796.02,1900 ; U18.1@1796.44,1865.79 v1(1796.44,1881.8)
  L1_Top Layer w10: v1(1291,1471.57) C37.1@1303.4,1471.57
  L6_Bottom Layer w5: v1(1291,1471.57) 1300.32,1462.26 C39.1@1300.32,1448.56 ; v1(1319,1299) 1319.98,1298.02 C38.1@1319.98,1281
  L6_Bottom Layer w10: R134.1@1794.07,2129.57 1851,2186.5 U16.8@1892.34,2186.5 U16.9@1892.34,2206.18
  L6_Bottom Layer w20: v1(1782.69,2091.95) v1(1803,2091.95) ; 1793,2102.26 R134.1@1793,2129.57 R134.1@1794.07,2129.57
IOVDD+: C79.1 C80.1 FB3.3 R134.2 U16.10 | length 319.3
  L6_Bottom Layer w10: FB3.3@1704.06,2261.3 1794,2261.3 1794,2193.56 R134.2@1793,2192.56 ; R134.2@1790.94,2194.62 R134.2@1793,2192.56 ; C80.1@1892.34,2270.01 U16.10@1892.34,2225.87 1845.37,2225.87 1812.06,2192.56 R134.2@1793,2192.56
NetC1_1: C1.1 J1.1 R2.2 | length 1144.8
  L1_Top Layer w14.5: C1.1@1233.42,1083.02 1250.64,1083.02 1250.69,1082.98 1287.91,1082.98 1328.89,1042 1328.89,517 1528.13,317.76 1528.13,289 ; v1(1505,290) 1527.13,290 1528.13,289 ; J1.1@1528.13,132 1528.13,289
  L6_Bottom Layer w14.5: R2.2@1488.75,290 v1(1505,290)
NetC1_2: C1.2 C3.2 R3.1 | length 24.4
  L1_Top Layer w5: R3.1@1187,1082.98 R3.1@1187,1082.98 C3.2@1211.37,1083.02
NetC2_1: C2.1 J2.1 | length 112
  L6_Bottom Layer w12: J2.1@1153.37,203 1153.37,249 C2.1@1153.37,315
NetC2_2: C2.2 T1.3 | length 203.1
  L1_Top Layer w14.5: v1(1154,360) 1206.92,360 1253.37,406.45 T1.3@1253.37,470
  L6_Bottom Layer w10: C2.2@1153.37,339.02 v1(1154,360)
NetC3_1: C3.1 T2.1 | length 64.5
  L1_Top Layer w14.5: C3.1@1211.37,1060.98 T2.1@1253.37,1011.98
NetC4_1: C4.1 L1.1 L2.2 R1.2 R3.2 R4.1 R7.2 | length 201.4
  L1_Top Layer w5: v1(1186.72,1120.69) 1186.72,1105.31 R3.2@1187,1105.02 ; R1.2@1210.72,1106 1209.74,1105.02 R3.2@1187,1105.02 ; L1.1@1237,1168.3 1209.71,1141.01 R4.1@1200,1141.01 1172.71,1141.01 L2.2@1170.7,1139 1164.99,1133.29 C4.1@1164.99,1105 R3.2@1187,1105.02
  L6_Bottom Layer w5: R7.2@1186.72,1096 v1(1186.72,1120.69)
NetC4_2: C4.2 L2.1 L3.1 R8.1 R10.2 R11.1 R14.2 | length 208.1
  L1_Top Layer w5: L3.1@1063.79,1168.3 1091.08,1141.01 R11.1@1100.69,1141.01 1131.29,1141.01 L2.1@1133.3,1139 1139.01,1133.29 C4.2@1139.01,1105 R10.2@1116.13,1105.02 ; R14.2@1090.6,1106 1091.57,1105.02 R10.2@1116.13,1105.02 ; v1(1116.98,1120.98) 1116.98,1105.87 R10.2@1116.13,1105.02
  L6_Bottom Layer w5: R8.1@1116.98,1096 v1(1116.98,1120.98)
NetC6_1: C6.1 T2.3 | length 61.4
  L1_Top Layer w14.5: T2.3@1053.37,1011.98 C6.1@1090.37,1060.98
NetC6_2: C6.2 C8.2 R10.1 | length 26
  L1_Top Layer w5: C8.2@1090.09,1082.98 R10.1@1116.13,1082.98
NetC7_2: C7.2 T1.5 T2.5 | length 122
  L1_Top Layer w14.5: T1.5@1153.37,670 T2.5@1153.37,792
  other v1: 1155,846.37
NetC8_1: C8.1 J3.1 R13.2 | length 1133
  L1_Top Layer w14.5: J3.1@778.13,132 778.13,291 ; v1(796.98,291) 778.13,291 ; C8.1@1063.02,1082.98 1056.12,1082.98 1018.35,1082.98 977.37,1042 977.37,517 778.13,317.76 778.13,291
  L6_Bottom Layer w10: v1(796.98,291) R13.2@815.98,291
NetC9_1: C9.1 J4.1 R16.2 | length 1200.2
  L1_Top Layer w5: 880.24,2364.24 882,2364.24
  L1_Top Layer w15: v1(868,2353) 880.24,2364.24
  L1_Top Layer w17: J4.1@755,2653 755,2491.24 882,2364.24 973.24,2273 973.24,1693 1026,1643 C9.1@1068.04,1642.95
  L6_Bottom Layer w7: R16.2@867.5,2336.52 867.5,2352.5 v1(868,2353)
NetC9_2: C9.2 C11.2 R17.1 | length 26.4
  L1_Top Layer w5: C11.2@1090.09,1642.95 1115.2,1642.95 R17.1@1116.13,1642.02
NetC10_1: C10.1 J5.1 | length 105.9
  L6_Bottom Layer w10: C10.1@1142,2441.1 J5.1@1142,2547
NetC10_2: C10.2 T3.3 | length 184.6
  L1_Top Layer w14.5: T3.3@1051,2291 1051,2346 v1(1085,2382)
  L6_Bottom Layer w10: v1(1085,2382) 1118.08,2382 1142,2405.92 C10.2@1142,2419.06
NetC11_1: C11.1 T4.1 | length 98.9
  L1_Top Layer w10: T4.1@1052,1690.57 T4.1@1052,1739.76 ; T4.1@1058,1703 C11.1@1090.09,1665
NetC12_1: C12.1 L4.1 L5.2 R15.2 R17.2 R18.1 R21.2 | length 172.3
  L1_Top Layer w5: L4.1@1071.55,1589.7 1101.29,1589.7 R18.1@1103,1587.99 1125.72,1587.99 L5.2@1132.67,1581.05 ; R15.2@1096.02,1619 1097,1619.98 R17.2@1116.13,1619.98 ; v1(1117.28,1603.72) 1116.13,1604.87 R17.2@1116.13,1619.98 ; L5.2@1133.67,1587.05 1138.01,1591.39 C12.1@1138.01,1620 R17.2@1116.13,1619.98
  L6_Bottom Layer w5: R21.2@1117.28,1590 v1(1117.28,1603.72)
NetC12_2: C12.2 L5.1 L6.1 R22.1 R24.2 R25.1 R28.2 | length 175.7
  L1_Top Layer w5: L5.1@1163.99,1591.39 C12.2@1163.99,1620 R24.2@1187,1619.98 ; L5.1@1170.07,1581.05 1177.02,1587.99 R25.1@1203,1587.99 1231.71,1587.99 L6.1@1233.42,1589.7 ; v1(1185.07,1603.93) 1187,1605.86 R24.2@1187,1619.98 ; R28.2@1212.98,1619 1212,1619.98 R24.2@1187,1619.98
  L6_Bottom Layer w5: R22.1@1185.07,1590 v1(1185.07,1603.93)
NetC14_1: C14.1 T4.3 | length 144
  L1_Top Layer w10: C14.1@1212.96,1663.82 1213.76,1663.86 1251,1704.82 T4.3@1251,1715.5 ; T4.3@1251,1739.76 T4.3@1251,1727.76 T4.3@1251,1715.5 ; T4.3@1252,1694.29 T4.3@1252,1716.6 ; T4.3@1252,1739.76 T4.3@1252,1716.6 ; T4.3@1256,1721 T4.3@1252,1716.6 ; T4.3@1251,1715.5 T4.3@1252,1716.6
NetC14_2: C14.2 C16.2 R24.1 | length 24.8
  L1_Top Layer w5: R24.1@1187,1642.02 1210.34,1642.02 C16.2@1211.39,1640.98
NetC15_2: C15.2 T3.5 T4.5 | length 263.2
  L1_Top Layer w14.5: T4.5@1151,1927.76 1153.02,1929.78 T3.5@1153.02,2101 ; T4.5@1152,1925.76 T4.5@1153,1926.76
  L1_Top Layer w20: T4.5@1151,1927.76 1152,1926.76 T4.5@1153.02,1927.78 ; v1(1152,1842) T4.5@1152,1925.76
  L6_Bottom Layer w14.5: v1(1152,1842) 1152.81,1842 C15.2@1153,1841.77
NetC16_1: C16.1 J6.1 R27.2 | length 1217.6
  L1_Top Layer w15: 1425,2360 v1(1436.5,2346.5)
  L1_Top Layer w17: C16.1@1234.02,1641.98 1279,1642.24 1328.89,1686 1329,2264 1425,2360 1528.24,2463.24 J6.1@1528.24,2675
  L6_Bottom Layer w7: R27.2@1436.5,2329.52 v1(1436.5,2346.5)
NetC17_1: C17.1 R34.1 R37.2 U1.2 | length 311.8
  L6_Bottom Layer w5: U1.2@2901.66,665.95 2935.05,665.95 2979,622 C17.1@2979,525.62 ; R34.1@2918,526 2978.62,526 C17.1@2979,525.62 ; R37.2@3037.76,525.62 C17.1@2979,525.62
NetC17_2: C17.2 J7.1 | length 283.9
  L6_Bottom Layer w5: C17.2@2979,478.38 2979,401 3031,349 J7.1@3164,349
NetC21_1: C21.1 C25.1 L7.2 R43.2 R45.2 R47.1 R48.2 | length 219.1
  L1_Top Layer w5: R45.2@747,1373.98 747.09,1373.89 R43.2@820.24,1373.89 ; R43.2@817,1374.24 857.51,1374.24 L7.2@858,1374.73 892.11,1374.73 C25.1@899,1381.62 920.41,1381.62 928.46,1389.67
  L1_Top Layer w12: 928.46,1389.67 R47.1@938.44,1389.67 C21.1@956.42,1389.67
NetC23_1: C23.1 J9.1 | length 137.3
  L6_Bottom Layer w12: J9.1@200,1359.65 201,1358.65 335.96,1358.65 C23.1@336.61,1359.3
NetC23_2: C23.2 T5.1 | length 141.9
  L1_Top Layer w12: T5.1@431,1461 433,1459 v1(433,1419)
  L6_Bottom Layer w12: C23.2@358.66,1359.3 373.3,1359.3 v1(433,1419)
NetC24_2: C24.2 R47.2 R50.1
NetC25_2: C25.2 C26.1 L7.1 R49.2 R50.2 R51.2 R53.2 | length 217.7
  L1_Top Layer w5: R49.2@746.02,1341.27 746.17,1341.41 R53.2@819.24,1341.41 ; R53.2@817,1341.76 857.51,1341.76 L7.1@858,1341.27 892.11,1341.27 C25.2@899,1334.38 922.71,1334.38 927.46,1329.63
  L1_Top Layer w12: 927.46,1329.63 R50.2@938.44,1329.63 C26.1@956.42,1329.63
NetC27_1: C27.1 C31.1 C34.1 L8.1 L9.1 L10.1 R57.2 TP1.1 | length 201.1
  L1_Top Layer w7: v1(2225.12,522.12) C27.1@2225.12,499 2254,499 2261.5,506.5 L8.1@2283.89,506.5
  L6_Bottom Layer w19.68: R57.2@2137.5,852.62 TP1.1@2208,852.62 ; C34.1@2428.62,966 2428.62,924.08 L10.1@2431.2,921.5
NetC44_2: C44.2 R78.2 | length 22.4
  L1_Top Layer w12: C44.2@1023,1509.56 R78.2@1023,1531.98
NetC46_1: C46.1 C47.1 C48.1 R75.1 R76.1 R77.1 TP2.1 | length 738.3
  L6_Bottom Layer w7: v1(1038,1332.5) 1055,1332.5
  L6_Bottom Layer w10: C47.1@873.18,1055 879.16,1049.02 994.68,1049.02 C46.1@994.68,1151 ; 994.68,1223.24 994.68,1234.68 1003.39,1243.39 1014.83,1243.39 ; R76.1@1055,1243.39 1055,1332.5 1055,1455 1063.84,1463.84 R77.1@1063.84,1490.84
  L6_Bottom Layer w12: TP2.1@873,974.8 873,1054.82 C47.1@873.18,1055 ; C46.1@994.68,1151 994.68,1223.24 ; 1014.83,1243.39 R76.1@1052.98,1243 ; 1023,1243 C48.1@1023.33,1224.59
NetC49_2: C49.2 R81.1 R82.2 R83.2 | length 158.4
  L6_Bottom Layer w14.5: R83.2@1348.45,435.62 1398.45,435.62 C49.2@1458.63,435.62 1458.63,387.63 R81.1@1458.76,387.5
NetC51_1: C51.1 L11.1 R84.2 | length 111.3
  L6_Bottom Layer w14.5: R84.2@1175,741.62 1175,833.74 L11.1@1188.56,847.3
NetC51_2: C51.2 L12.1 R90.2 | length 109.8
  L6_Bottom Layer w14.5: L12.1@1121.51,848.3 1129,840.81 R90.2@1129,741.62
NetC53_1: C53.1 R91.1 R92.1 R94.1 | length 160.3
  L6_Bottom Layer w14.5: R94.1@846.12,383 845.62,383.5 C53.1@845.62,431.62 R91.1@901.07,431.62 ; R91.1@901.45,431.62 R92.1@957.45,431.62
NetC54_2: C54.2 R98.1 R99.2 R100.2 | length 147
  L6_Bottom Layer w14.5: C54.2@908.38,2388 R98.1@908.38,2437 ; R99.2@909.32,2341.62 R100.2@959.62,2341.62 ; R99.2@910,2342.3 C54.2@910,2390
NetC56_1: C56.1 L13.1 R101.2 | length 167.1
  L6_Bottom Layer w14.5: L13.1@1105.47,1868.7 1105.47,1912.47 1125.75,1932.75 C56.1@1125.75,1960 ; C56.1@1128.9,1960.22 R101.2@1128.9,2027.62
NetC56_2: C56.2 L14.1 R107.2 | length 169.1
  L6_Bottom Layer w14.5: C56.2@1172.99,1960 1172.99,1934.01 1194.53,1912.47 1194.53,1875.21 L14.1@1201.04,1868.7 ; C56.2@1174.9,1960.22 R107.2@1174.9,2026.38
NetC58_1: C58.1 R109.1 R110.1 R111.1 | length 146
  L6_Bottom Layer w14.5: R109.1@1341,2337.62 R110.1@1392,2337.62 1391.62,2338 C58.1@1391.62,2384.38 ; C58.1@1390.12,2384.38 R111.1@1390.12,2432.5
NetC67_1: C67.1 C68.1 J16.2 L15.1 | length 331.9
  L6_Bottom Layer w30: L15.1@2443.62,2528 2471,2528 2496,2553 C68.1@2536,2553 ; J16.2@2510,2659 2510,2624 2536,2598 C68.1@2536,2553 ; C67.1@2536.91,2441 2536,2441.91 C68.1@2536,2553
NetC69_1: C69.1 FB1.1 L15.2 R114.2 | length 335.1
  L6_Bottom Layer w30: FB1.1@2256.91,2449 2315,2449 2329,2463 2385.8,2463 C69.1@2388.8,2466 L15.2@2388.8,2520.42 ; R114.2@2271,2567.62 2356.76,2567.62 L15.2@2396.38,2528
NetC71_2: C71.2 R115.1 R119.2 U8.1 U8.2
NetC72_2: C72.2 R117.1 R120.2 U9.1 U9.2
NetC74_1: C74.1 FB2.1 R115.2 | length 163.1
  L6_Bottom Layer w15: R115.2@601,2128.5 763.7,2128.5 FB2.1@764,2128.8
NetC78_1: C78.1 FB3.1 R117.2
NetC81_1: C81.1 U10.1 | length 93.3
  L6_Bottom Layer w15: U10.1@1957.16,355.4 1969.67,355.4 C81.1@2026.78,412.5
NetC81_2: C81.2 U10.8 | length 92.4
  L6_Bottom Layer w15: U10.8@1957.16,530.6 1971.67,530.6 C81.2@2026.78,475.5
NetC82_1: C82.1 U11.1 | length 57.7
  L1_Top Layer w10: U11.1@522.9,2289.88 555,2289.88 v1(555.12,2290)
  L6_Bottom Layer w10: v1(555.12,2290) C82.1@580.5,2290
NetC82_2: C82.2 U11.8 | length 54.7
  L1_Top Layer w10: v1(669,2290) 669.12,2289.88 U11.8@698.1,2289.88
  L6_Bottom Layer w10: C82.2@643.5,2290 v1(669,2290)
NetC84_1: C84.1 L18.1 U12.5 | length 176.6
  L6_Bottom Layer w5: C84.1@2167,2259.5 2167,2180.62 L18.1@2166,2179.62 2195.52,2179.62 2226,2149.15 2249.32,2149.15 U12.5@2249.6,2148.87
NetC87_1: C87.1 R123.1 U10.6 | length 219.2
  L6_Bottom Layer w15: R123.1@1773.62,614.98 C87.1@1907,616 1905.98,614.98 U10.6@1905.98,530.6
NetC89_1: C89.1 R124.1 U11.6 | length 64.1
  L1_Top Layer w10: v1(732,2239.19) 761.19,2239.19 R124.1@761.38,2239
  L6_Bottom Layer w10: C89.1@730,2273 730,2241.19 v1(732,2239.19)
NetC91_1: C91.1 U10.7 | length 71
  L1_Top Layer w15: v1(1932.5,490.5) C91.1@1932.5,521.01
  L6_Bottom Layer w5: v1@1931.57,491.43 v1(1932.5,490.5)
  L6_Bottom Layer w15: v1@1931.57,491.43 U10.7@1931.57,530.6
NetC92_1: C92.1 U11.7 | length 35.5
  L1_Top Layer w10: v1(665,2256) U11.7@675,2266 ; U11.7@676.71,2264.29 U11.7@698.1,2264.29
NetC94_1: C94.1 R125.2 U10.4 | length 146.2
  L6_Bottom Layer w15: R125.2@1808.78,280.62 C94.1@1808.78,355 1879.99,355 U10.4@1880.39,355.4
NetC96_1: C96.1 R126.2 U11.4 | length 130.4
  L1_Top Layer w15: C96.1@481.5,2150.01 481.5,2177.5 463.12,2195.88 R126.2@463.12,2213.01 522.81,2213.01 U11.4@522.9,2213.11
NetC98_1: C98.1 R129.1 U13.1 | length 210.5
  L1_Top Layer w10: U13.1@840.87,1666.4 873.57,1666.4 893.5,1644.5 914.5,1623.5 914.5,1536 C98.1@945.48,1536
NetC98_2: C98.2 R127.2 R128.1 U13.4 | length 127.5
  L1_Top Layer w10: U13.4@949.13,1591.6 R127.2@1005.4,1594.05 ; U13.4@958.29,1582.71 966.52,1574.48 C98.2@967.52,1536 R128.1@967.52,1514.95
NetC101_1: C101.1 R131.2 R132.2 U13.3 | length 145.5
  L1_Top Layer w10: U13.3@840.87,1591.6 v1(869,1595) ; U13.3@852,1582 R131.2@852.02,1556.02 853.02,1555.02 R132.2@853.02,1531
  L6_Bottom Layer w10: C101.1@806,1611.44 820.56,1611.44 v1(869,1595)
NetC111_1: C111.1 C112.2 L19.2 U17.9 | length 207.5
  L6_Bottom Layer w5: U17.9@2755.56,2091.47 2797.45,2091.47 C112.2@2798,2092.02 2870,2092.02 2875.53,2086.5 C111.1@2897,2086.5 2897.5,2086 L19.2@2960.38,2086
NetC113_1: C113.1 C114.2 L20.2 U17.5 | length 215.1
  L6_Bottom Layer w5: U17.5@2755.56,2170.21 2756.27,2169.5 L20.2@2853.38,2169.5 2853.38,2199 2865,2210.62 C113.1@2865,2231.5 2865.53,2230.98 C114.2@2915,2230.98
NetC115_1: C115.1 R149.2 R152.2 R153.2 U18.11 | length 112.5
  L1_Top Layer w5: C115.1@1881.76,1864.79 C115.1@1881.98,1865
  L1_Top Layer w7: U18.11@1851.56,1864.79 C115.1@1881.76,1864.79
  L1_Top Layer w12: R149.2@1846.02,1911 R152.2@1881.98,1911 R153.2@1881.98,1888 C115.1@1881.98,1865
NetC117_1: C117.1 R155.2 U17.11 | length 96
  L6_Bottom Layer w5: U17.11@2755.56,2052.1 2756.26,2051.4 C117.1@2820,2051.4 2820.62,2052.02 R155.2@2851,2052.02
NetC118_1: C118.1 U17.3 Y5.1 | length 201.9
  L1_Top Layer w5: v1(2783,2209) 2783,2238.31 C118.1@2758,2263.31 2761.18,2266.5 2807.83,2266.5 2811.02,2263.31 2851.61,2263.31 Y5.1@2861,2272.71
  L6_Bottom Layer w5: U17.3@2755.56,2209.58 2756.14,2209 v1(2783,2209)
NetC119_1: C119.1 U17.4 Y5.2 | length 279.4
  L1_Top Layer w5: v1(2807,2191) 2861.98,2136.02 2861.98,2110.31 C119.1@2986,2110.31
  L6_Bottom Layer w5: U17.4@2755.56,2189.9 2805.9,2189.9 v1(2807,2191)
NetC124_1: C124.1 R165.1 R166.1 R173.2 R174.2 U23.5 | length 254.2
  L6_Bottom Layer w10: C124.1@2468.98,1720 2468.98,1719.43 U23.5@2420.29,1719.43 2420.29,1705.71 R173.2@2448.66,1677.34 2477.02,1648.98 R166.1@2526,1648.98 R165.1@2588,1648.98
NetC125_2: C125.2 U8.6 | length 50
  L6_Bottom Layer w12: U8.6@460.07,2372.62 C125.2@460.07,2422.62
NetC126_2: C126.2 U9.6 | length 50
  L6_Bottom Layer w12: U9.6@1549.2,2306.65 C126.2@1549.2,2356.65
NetD1_2: D1.2 R59.1 | length 175.5
  L1_Top Layer w7: D1.2@2315.9,1030 2317,1028.9 v1(2317,879)
  L6_Bottom Layer w7: R59.1@2317,855 v1(2317,879)
NetD2_2: D2.2 R114.1 | length 85.7
  L1_Top Layer w10: v1(2306,2503) 2307,2502 D2.2@2349.1,2502
  L6_Bottom Layer w10: R114.1@2271,2520.38 2288.38,2503 v1(2306,2503)
NetJ11_1: J11.1 U3.14 | length 381.6
  L1_Top Layer w7: U3.14@2453.53,771.8 2453.53,825.68 2504.85,877 J11.1@2760,877
NetJ12_1: J12.1 U3.10 | length 737.7
  L1_Top Layer w7: U3.10@2498.8,706.84 3048.84,706.84 3091,749 J12.1@3091,877
NetL1_2: L1.2 R6.1 | length 28.8
  L1_Top Layer w5: R6.1@1210.02,1210 1232.7,1210 L1.2@1237,1205.7
NetL3_2: L3.2 R9.1 | length 28
  L1_Top Layer w5: L3.2@1063.79,1205.7 1068.09,1210 R9.1@1089.98,1210
NetL4_2: L4.2 R20.1 | length 33
  L1_Top Layer w5: L4.2@1071.55,1552.3 1089.85,1534 R20.1@1096.98,1534
NetL6_2: L6.2 R23.1 | length 33
  L1_Top Layer w5: R23.1@1208.02,1534 1214,1534 1232.3,1552.3 L6.2@1233.42,1552.3
NetR4_2: R4.2 R5.1 R6.2 | length 73.4
  L1_Top Layer w5: R5.1@1163.85,1213.01 1166.86,1210 R6.2@1187.98,1210 1187.98,1196.02 1200,1184 R4.2@1200,1166.99
NetR9_2: R9.2 R11.2 R12.1 | length 78.9
  L1_Top Layer w5: R11.2@1100.69,1166.99 1100.69,1183.67 1112.02,1195 R9.2@1112.02,1210 1138.99,1210 R12.1@1142,1213.01
NetR18_2: R18.2 R19.1 R20.2 | length 57
  L1_Top Layer w5: R18.2@1103,1562.01 1103,1560.02 1119.02,1544 R20.2@1119.02,1534 1139.99,1534 R19.1@1141,1532.99
NetR23_2: R23.2 R25.2 R26.1 | length 56
  L1_Top Layer w5: R26.1@1163,1532.99 R23.2@1183.97,1532.99 ; R23.2@1185.98,1534 1185.98,1543.98 1203,1561 R25.2@1203,1562.01
NetR29_1: R29.1 R30.1 Y1.3 Y2.3 | length 847.7
  L1_Top Layer w5: v1(849,1457) 923,1456 925,1454 955.98,1433.9 R30.1@955.98,1420
  L1_Top Layer w10: v1@663.14,1769 v1(663.39,1768.76)
  L3_Signal w10: v1(663.39,1768.76) 643,1748.37 643,1467 654,1456 v1(849,1457)
  L6_Bottom Layer w10: Y2.3@663.31,1911.08 Y1.3@663.31,1967.55 ; v1(663.39,1768.76) 663.14,1769 663.14,1833.05 663.39,1833.29 Y2.3@663.39,1893 ; v1(849,1457) 849.15,1456.85 R29.1@849.15,1439.02
NetR31_1: R31.1 R33.2 Y1.1 | length 130.6
  L6_Bottom Layer w10: R31.1@502.02,2095 502.02,2040.85 506.43,2036.45 Y1.1@576.69,2036.45
NetR32_1: R32.1 R35.1 U1.7 | length 70.3
  L1_Top Layer w7: R32.1@2683.02,666 v1(2702,666)
  L6_Bottom Layer w7: R35.1@2683.02,666 v1(2702,666) 2734.28,666 U1.7@2734.34,665.95
NetR36_1: R36.1 R40.1 U1.6 | length 71.7
  L1_Top Layer w7: R40.1@2683.02,642 2684.67,640.35 v1(2702,640.35)
  L6_Bottom Layer w7: R36.1@2683.02,642 2700.35,642 v1(2702,640.35) U1.6@2734.34,640.35
NetR38_1: R38.1 R39.2 Y2.1 | length 200.2
  L6_Bottom Layer w10: R38.1@249,1665 249,1695 ; R39.2@251,1775.98 249,1773.98 249,1695 ; Y2.1@336.61,1693 251,1693 249,1695
NetR42_1: R42.1 R44.2 U1.3 | length 228.7
  L6_Bottom Layer w5: R44.2@2738,547.62 R42.1@2794,547.62 2794,593 2841.35,640.35 U1.3@2901.66,640.35
NetR48_1: R48.1 T5.6 | length 128.1
  L1_Top Layer w14.5: T5.6@643,1457.3 660.66,1457.3 724.98,1392.99 R48.1@724.98,1373.54
NetR49_1: R49.1 T5.4 | length 128.5
  L1_Top Layer w14.5: T5.4@643,1257.3 661.39,1257.3 724.98,1320.89 R49.1@724.98,1341.06
NetR52_1: R52.1 R55.2 U2.7 | length 68.5
  L6_Bottom Layer w10: U2.7@1666.94,1455 1666.94,1486.92 R52.1@1668.02,1488 1702.79,1488 R55.2@1702.98,1488.19
NetR60_2: R60.2 Y3.1 | length 122
  L1_Top Layer w7: Y3.1@2272.57,387.28 2322.27,436.98 R60.2@2374,436.98
NetR61_1: R61.1 U3.18 | length 372.7
  L1_Top Layer w5: U3.18@2374.79,771.8 2374.79,786.11 2379.63,790.96 2379.63,949.14 2459,1028 ; 2459,1028.5 2534,1028.5 R61.1@2538.84,1032.84
NetR63_2: R63.2 Y3.3 | length 161.4
  L1_Top Layer w7: Y3.3@2343.43,296.72 2394.47,347.76 R63.2@2394.47,436.98
NetR64_1: R64.1 U3.17 | length 355.6
  L1_Top Layer w5: 2389.63,790.96 2394.47,786.11 U3.17@2394.47,771.8 ; 2390.13,790.96 2390.13,945 2464,1018 2534,1018 R64.1@2538.84,1013.66
NetR65_1: R65.1 Y4.4 | length 93.7
  L6_Bottom Layer w7: Y4.4@2428,405.98 R65.1@2520.87,405.98 ; Y4.4@2440.38,403.58 Y4.4@2440.96,403
NetR66_1: R66.1 R69.2 Y4.1 | length 146.4
  L6_Bottom Layer w7: R69.2@2049,184.02 2049,204 ; R66.1@2049,217.98 2049,204 ; Y4.1@2161.04,203 2050,203 2049,204
NetR68_1: R68.1 Y4.2 | length 100.4
  L6_Bottom Layer w7: R68.1@2061.02,304 2062.02,303 Y4.2@2161.04,303
NetR71_2: R71.2 U3.8 | length 40.6
  L1_Top Layer w7: U3.8@2498.8,667.47 v1(2521.47,667.47)
  L6_Bottom Layer w7: R71.2@2503.99,668.47 2520.47,668.47 v1(2521.47,667.47)
NetR79_1: R79.1 TP8.1 | length 313.8
  L6_Bottom Layer w5: TP8.1@810,1748 985.71,1572.29 R79.1@985.71,1506.99
NetR80_1: R80.1 R86.2 U6.2 | length 210.5
  L6_Bottom Layer w5: U6.2@1161.76,531 1159.54,528.78 1159.54,480.29 1166.61,473.22
  L6_Bottom Layer w14.5: 1166.61,473.22 1197.95,441.88 1203.89,441.88 1208.45,437.32 R80.1@1208.45,433.38 ; R80.1@1209.2,430.62 R86.2@1297.45,430.62
NetR80_2: R80.2 U6.1 | length 63.6
  L6_Bottom Layer w14.5: U6.1@1181.45,531 1181.45,505.62 R80.2@1208.45,478.62
NetR84_1: R84.1 U6.11 | length 62.4
  L6_Bottom Layer w5: U6.11@1161.76,641.24 1159.54,643.46 1159.54,678.2 1162.47,681.13 1165.69,681.13 1175,690.44 R84.1@1175,694.38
